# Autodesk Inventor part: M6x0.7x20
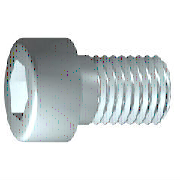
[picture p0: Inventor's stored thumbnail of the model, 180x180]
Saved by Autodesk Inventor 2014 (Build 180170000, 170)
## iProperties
Created: 2009-02
Part Number: M6x0.7x20
Material: 강, 연강
Description: 6각머리 태핑 나사
Document SubType Name: Modeling
Standard: KS B 1003
Designer: KYOUNG IL JANG
Standards Organization: KS
Language: ko-KR
Size Designation: M 6 x 20
Categories: <MemberInstance><Categories><Category DisplayName="조임쇠" InternalName="e4da775c-781d-43d5-af7c-5136215cf5a6" Mnemonic="FSTN"><Category DisplayName="볼트" InternalN
Density: 7.86 g/cm^3
Mass: 7.48273 g
Surface Area: 7.64101 cm^2
Volume: 0.952001 cm^3
Vendor: CBT Solutions
Appearance: 연마 - 진회색
Company: 한국ATC센터
IsCustomPart: 1
Author: KYOUNG IL JANG
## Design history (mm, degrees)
sketch "스케치1"
  geometry: L1 (-1.333, 0)-(20, 0); L2 (20, 0)-(20, 3); L3 (20, 3)-(2.5, 3); L4 (2.5, 3)-(1.886, 3); L5 (1.886, 3)-(0, 3); L6 (0, 3)-(0, 5); L7 (0, 5)-(-6, 5); L8 (-6, 5)-(-6, 2.887); L9 (-6, 2.887)-(-3, 2.887); L10 (-3, 2.887)-(-1.333, 0); L11 (-11.2, 0)-(25.2, 0) reference; L12 (0, -1)-(0, 6) reference; L13 (2.5, 3)-(0, 3)
  constraints: 22 end point, 6 parallel, 2 collinear, 2 perpendicular, 1 horizontal, 1 point on line
  dimensions: "d1" = 17.5 distance from line of L3.end L2 (= GEL); "d2" = 0.61355 distance of L4.end L3.end (computed from GAL); "d3" = 6 distance between parallel lines of L8 L6 (= KOH); "d4" = 3 distance of L8.end L9.end (= INTI); "d5" = 60 deg angle of L10 L1; "d6" = 6 diameter of L3 L1 (= GD); "d7" = 6 diameter of L5 L1 (= BDM); "d8" = 5.7735 diameter of L9 L1 (= 1.1547 x SW); "d9" = 10 diameter of L7 L1 (= KOD); "d26" = 20 distance between parallel lines of L12 L2 (= NLG)
revolve "본체" sketch "스케치1" stored, may be unused: angle "d10" = 90 deg
sketch "스케치2"
  geometry: L1 (0, -7)-(0, 7) reference; L2 (-7, 0)-(7, 0) reference; L3 (2.887, 0)-(1.443, -2.5); L4 (1.443, -2.5)-(-1.443, -2.5); L5 (-1.443, -2.5)-(-2.887, 0); L6 (-2.887, 0)-(-1.443, 2.5); L7 (-1.443, 2.5)-(1.443, 2.5); L8 (1.443, 2.5)-(2.887, 0); 2 further points
  constraints: 12 end point, 1 coincident, 1 horizontal alignment, 1 point on line, 12 other
extrude "슬롯" join sketch "스케치2" stored distance "d11" = 10; taper "d12" = 0 deg
workplane "Work Plane1"
fillet "Fillet2" dims "d30" = 0.1 (= R)
body "Solid1"
fillet "모깎기1" dims "d17" = 0.6 (= RR)
feature "스레드" dims "d13" = 17.5 (= GEL), "d14" = 0
chamfer "모따기1" distance "d15" = 0.61345 (= -0.5 x SPD + 0.5 x GD); stored, may be unused: second distance "d16" = 0.61345 (= GUL), angle "d27" = 45 deg
other parameters: "GD" = 6 (= NND) [user parameter; used in 2 equation terms], "NLG" = 20 [user parameter; used in 1 equation term], "GEL" = 17.5 [user parameter; used in 2 equation terms], "KOD" = 10 [user parameter; used in 1 equation term], "KOH" = 6 [user parameter; used in 1 equation term], "INTI" = 3 [user parameter; used in 1 equation term], "GAL" = 0.61345 (= 0.61345 x PTC) [user parameter; used in 1 equation term], "GUL" = 0.61345 (= 0.61345 x PTC) [user parameter; used in 1 equation term], "BDM" = 6 (= NND) [user parameter; used in 1 equation term], "SW" = 5 [user parameter; used in 2 equation terms], "RR" = 0.6 [user parameter; used in 1 equation term], "SPD" = 4.7731 (= NND - 1.2269 x PTC) [user parameter; used in 1 equation term], "d19" = 0, "d28" = 0, "d29" = 0, "R" = 0.1 [user parameter; used in 1 equation term], "PHH" = 0.25 [user parameter], "GD1" = 4.7731 (= THREADDIA - 1.2269 x PTC) [user parameter], "THREADDIA" = 6 [user parameter; used in 1 equation term], "FAWI" = 45 deg [user parameter], "PTC" = 1 [user parameter; used in 5 equation terms], "NND" = 6 [user parameter; used in 3 equation terms], "TOA" = 30 deg [user parameter], "E0" = 5.775 (= 1.155 x SW) [user parameter]
